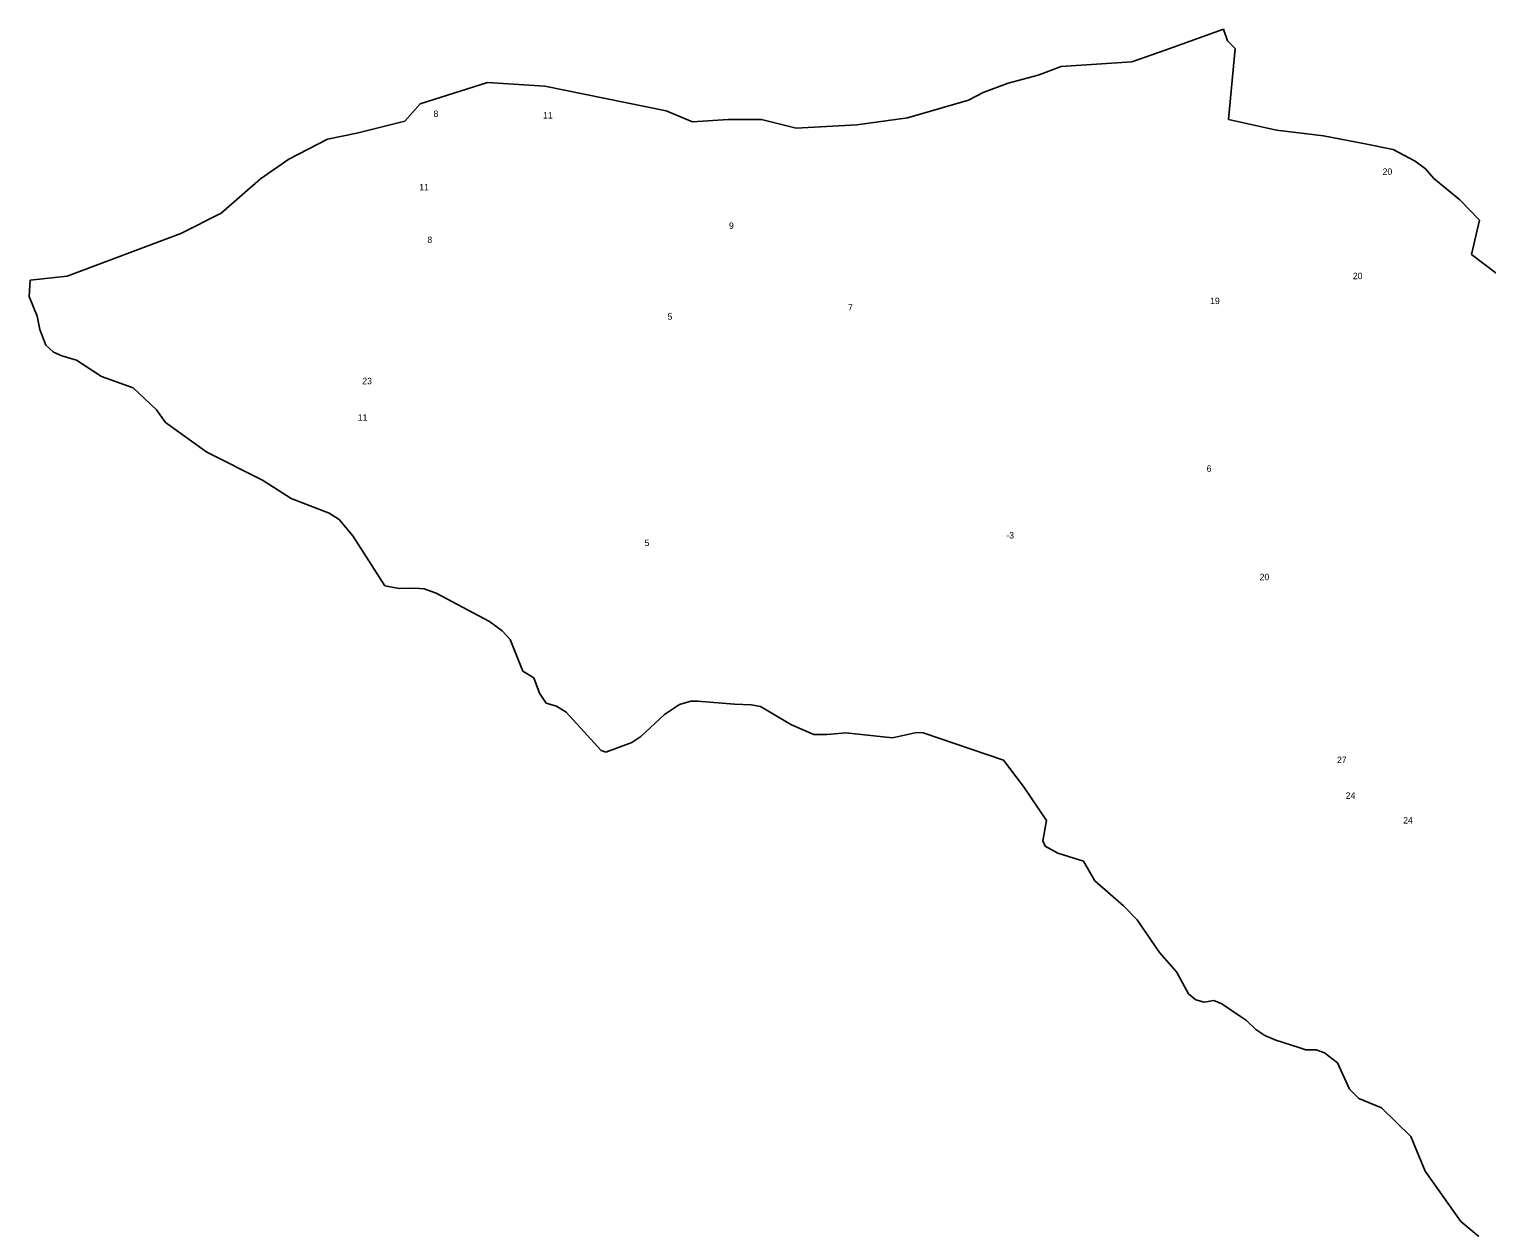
# Model space of a CAD drawing. Extents: x -790660 to -787188, y -969557 to -965825.
# Drawn here: x -790660 to -788400, y -967686 to -965825 of the extents above; entities that cross this region are included whole.
import ezdxf

# ---------------------------------------------------------------- set-up
doc = ezdxf.new("R2010")
doc.units = 0
for name, color, linetype in [('Vrstva 13', 7, 'Continuous'), ('Vrstva 15', 7, 'Continuous'), ('Vrstva 63', 7, 'Continuous')]:
    doc.layers.add(name, color=color, linetype=linetype)

msp = doc.modelspace()

# ---------------------------------------------------------------- linework, layer by layer
at = {"layer": 'Vrstva 13'}
for p, q in [((-788898.53, -965857.94), (-788807.85, -965825.22)), ((-788807.85, -965825.22), (-788801.53, -965843.6)), ((-788801.53, -965843.6), (-788790.05, -965855.08)), ((-788950.19, -965875.74), (-788898.53, -965857.94)), ((-788790.05, -965855.08), (-788800.38, -965965.33)), ((-789095.41, -965896.41), (-789059.82, -965883.21)), ((-789059.82, -965883.21), (-788950.19, -965875.74)), ((-790053.95, -965941.2), (-789949.49, -965907.9)), ((-789949.49, -965907.9), (-789860.52, -965913.64)), ((-789860.52, -965913.64), (-789672.26, -965952.11)), ((-789180.36, -965923.4), (-789141.9, -965909.05)), ((-789141.9, -965909.05), (-789095.41, -965896.41)), ((-789298.02, -965963.01), (-789203.32, -965935.45)), ((-789203.32, -965935.45), (-789180.36, -965923.4)), ((-790077.48, -965968.2), (-790053.95, -965941.2)), ((-789672.26, -965952.11), (-789631.5, -965968.76)), ((-790152.1, -965986.57), (-790077.48, -965968.2)), ((-789631.5, -965968.76), (-789575.83, -965965.31)), ((-789575.83, -965965.31), (-789524.17, -965965.31)), ((-789524.17, -965965.31), (-789470.79, -965979.09)), ((-789470.79, -965979.09), (-789376.66, -965973.92)), ((-789376.66, -965973.92), (-789298.02, -965963.01)), ((-788800.38, -965965.33), (-788725.63, -965981.84)), ((-790257.13, -966026.77), (-790197.44, -965995.76)), ((-790197.44, -965995.76), (-790152.1, -965986.57)), ((-788725.63, -965981.84), (-788652.73, -965990.74)), ((-788652.73, -965990.74), (-788588.16, -966003.08)), ((-788588.16, -966003.08), (-788544.67, -966012.12)), ((-790301.33, -966057.2), (-790257.13, -966026.77)), ((-788544.67, -966012.12), (-788510.67, -966029.78)), ((-788510.67, -966029.78), (-788494.89, -966041.84)), ((-788494.89, -966041.84), (-788481.97, -966057.06)), ((-790362.17, -966110.6), (-790301.33, -966057.2)), ((-788481.97, -966057.06), (-788441.51, -966090.07)), ((-788441.51, -966090.07), (-788410.8, -966121.65)), ((-790424.73, -966142.18), (-790362.17, -966110.6)), ((-788410.8, -966121.65), (-788423.28, -966174.91)), ((-790600.94, -966208.21), (-790424.73, -966142.18)), ((-788423.28, -966174.91), (-788384.97, -966203.76)), ((-790658.74, -966214.38), (-790660.07, -966240.06)), ((-790658.74, -966214.38), (-790600.94, -966208.21)), ((-790660.07, -966240.06), (-790647.74, -966270.74)), ((-790647.74, -966270.74), (-790643.74, -966291.08)), ((-790643.74, -966291.08), (-790634.41, -966315.43)), ((-790634.41, -966315.43), (-790622.4, -966326.43)), ((-790622.4, -966326.43), (-790609.4, -966331.77)), ((-790609.4, -966331.77), (-790586.4, -966338.77)), ((-790586.4, -966338.77), (-790548.07, -966364.11)), ((-790548.07, -966364.11), (-790498.73, -966381.46)), ((-790498.73, -966381.46), (-790462.4, -966415.81)), ((-790462.4, -966415.81), (-790448.73, -966435.48)), ((-790448.73, -966435.48), (-790384.39, -966481.5)), ((-790384.39, -966481.5), (-790298.39, -966524.85)), ((-790298.39, -966524.85), (-790281.06, -966535.86)), ((-790281.06, -966535.86), (-790253.72, -966553.2)), ((-790253.72, -966553.2), (-790194.73, -966575.87)), ((-790194.73, -966575.87), (-790179.06, -966585.87)), ((-790179.06, -966585.87), (-790158.06, -966611.22)), ((-790158.06, -966611.22), (-790108.72, -966688.92)), ((-790108.72, -966688.92), (-790086.39, -966692.92)), ((-790086.39, -966692.92), (-790062.06, -966692.58)), ((-790062.06, -966692.58), (-790047.39, -966693.58)), ((-790047.39, -966693.58), (-790029.06, -966700.25)), ((-790029.06, -966700.25), (-789946.39, -966744.27)), ((-789946.39, -966744.27), (-789926.72, -966758.61)), ((-789926.72, -966758.61), (-789914.38, -966772.28)), ((-789914.38, -966772.28), (-789894.38, -966821.31)), ((-789894.38, -966821.31), (-789877.38, -966831.65)), ((-789877.38, -966831.65), (-789868.71, -966855.32)), ((-789868.71, -966855.32), (-789858.05, -966871)), ((-789858.05, -966871), (-789842.38, -966875.67)), ((-789842.38, -966875.67), (-789827.04, -966885)), ((-789827.04, -966885), (-789773.04, -966944.36)), ((-789675.03, -966888.32), (-789651.7, -966872.98)), ((-789651.7, -966872.98), (-789634.03, -966867.98)), ((-789634.03, -966867.98), (-789623.36, -966867.65)), ((-789623.36, -966867.65), (-789566.02, -966872.32)), ((-789566.02, -966872.32), (-789540.36, -966873.32)), ((-789540.36, -966873.32), (-789525.69, -966875.98)), ((-789525.69, -966875.98), (-789478.02, -966904.66)), ((-789711.7, -966922.67), (-789675.03, -966888.32)), ((-789478.02, -966904.66), (-789443.02, -966919.67)), ((-789725.7, -966932.01), (-789711.7, -966922.67)), ((-789443.02, -966919.67), (-789422.68, -966919.67)), ((-789422.68, -966919.67), (-789393.68, -966917)), ((-789393.68, -966917), (-789321.34, -966924.67)), ((-789321.34, -966924.67), (-789284.01, -966916.33)), ((-789284.01, -966916.33), (-789273.67, -966917)), ((-789273.67, -966917), (-789149.33, -966959.02)), ((-789773.04, -966944.36), (-789765.71, -966947.03)), ((-789765.71, -966947.03), (-789725.7, -966932.01)), ((-789149.33, -966959.02), (-789118, -967000.04)), ((-789118, -967000.04), (-789082.33, -967053.07)), ((-789082.33, -967053.07), (-789088.33, -967084.41)), ((-789088.33, -967084.41), (-789084.66, -967092.75)), ((-789084.66, -967092.75), (-789064.99, -967103.76)), ((-789064.99, -967103.76), (-789024.99, -967115.76)), ((-789024.99, -967115.76), (-789007.66, -967146.44)), ((-789007.66, -967146.44), (-788962.99, -967185.46)), ((-788962.99, -967185.46), (-788941.99, -967206.8)), ((-788941.99, -967206.8), (-788907.32, -967257.49)), ((-788907.32, -967257.49), (-788880.99, -967287.5)), ((-788880.99, -967287.5), (-788861.98, -967321.52)), ((-788861.98, -967321.52), (-788850.65, -967330.85)), ((-788850.65, -967330.85), (-788837.98, -967334.52)), ((-788837.98, -967334.52), (-788822.65, -967332.19)), ((-788822.65, -967332.19), (-788810.31, -967337.52)), ((-788810.31, -967337.52), (-788781.31, -967356.86)), ((-788781.31, -967356.86), (-788771.98, -967363.2)), ((-788771.98, -967363.2), (-788757.65, -967376.87)), ((-788757.65, -967376.87), (-788743.64, -967386.21)), ((-788743.64, -967386.21), (-788726.98, -967393.55)), ((-788726.98, -967393.55), (-788691.31, -967404.88)), ((-788691.31, -967404.88), (-788679.97, -967408.55)), ((-788679.97, -967408.55), (-788664.31, -967408.55)), ((-788664.31, -967408.55), (-788651.31, -967413.22)), ((-788651.31, -967413.22), (-788631.3, -967428.89)), ((-788631.3, -967428.89), (-788612.64, -967469.58)), ((-788612.64, -967469.58), (-788597.97, -967484.25)), ((-788597.97, -967484.25), (-788562.97, -967498.59)), ((-788562.97, -967498.59), (-788517.3, -967542.94)), ((-788517.3, -967542.94), (-788494.96, -967596.97)), ((-788494.96, -967596.97), (-788439.62, -967674.68)), ((-788439.62, -967674.68), (-788411.95, -967698.02))]:
    msp.add_line(p, q, dxfattribs=at)

# ---------------------------------------------------------------- texts
at = {"layer": 'Vrstva 15'}
for s, p in [('8', (-790032.996, -965961.51)), ('11', (-789863.056, -965963.89)), ('20', (-788561.086, -966051.31)), ('11', (-790054.996, -966075.31)), ('9', (-789574.81, -966135.16)), ('8', (-790042.476, -966157.09)), ('20', (-788607.296, -966213.1)), ('7', (-789390.256, -966261.98)), ('19', (-788828.584, -966251.79)), ('5', (-789670.146, -966276.07)), ('23', (-790143.436, -966376.06)), ('11', (-790150.386, -966432.68)), ('6', (-788834, -966511.94)), ('-3', (-789144.64, -966615.33)), ('5', (-789705.696, -966627.21)), ('20', (-788751.846, -966680.13)), ('24', (-788618.342, -967019.26)), ('24', (-788529.302, -967057.55))]:
    msp.add_text(s, height=10, dxfattribs=at).set_placement(p)
at = {"layer": 'Vrstva 63'}
msp.add_text('27', height=10, dxfattribs=at).set_placement((-788631.876, -966963.8))

doc.saveas('drawing.dxf')
